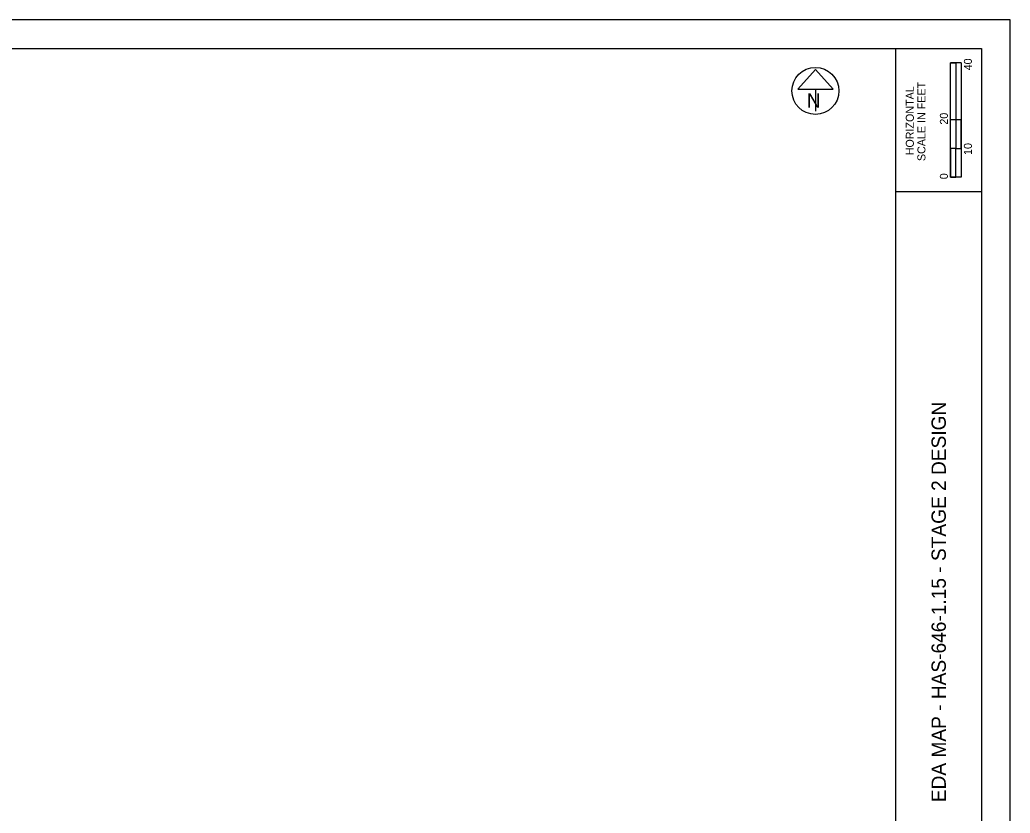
# Model space of a CAD drawing. Extents: x 117359.7 to 117393.7, y 12355.1 to 12408.1.
# Drawn here: x 117376.39 to 117393.71, y 12394.19 to 12408.06 of the extents above; entities that cross this region are included whole.
import ezdxf

# ---------------------------------------------------------------- set-up
doc = ezdxf.new("R2010")
doc.units = 0
for name, color, linetype in [('SH_Border', 7, 'Continuous'), ('SH_Cut_Line', 7, 'Continuous'), ('SH_Data', 7, 'Continuous'), ('SH_Masking', 7, 'Continuous'), ('SH_Text', 7, 'Continuous')]:
    doc.layers.add(name, color=color, linetype=linetype)

msp = doc.modelspace()

# ---------------------------------------------------------------- linework, layer by layer
at = {"layer": 'SH_Border'}
for p, q in [((117391.708, 12386.562), (117391.708, 12407.562)), ((117391.708, 12405.062), (117393.208, 12405.062))]:
    msp.add_line(p, q, dxfattribs=at)
msp.add_lwpolyline([(117361.208, 12407.562), (117393.208, 12407.562), (117393.208, 12386.562), (117361.208, 12386.562)], close=True, dxfattribs=at)
at = {"layer": 'SH_Cut_Line'}
msp.add_lwpolyline([(117359.708, 12386.062), (117393.708, 12386.062), (117393.708, 12408.062), (117359.708, 12408.062)], close=True, dxfattribs=at)
at = {"layer": 'SH_Data'}
for p, q in [((117392.665, 12405.312), (117392.665, 12407.312)), ((117392.853, 12407.312), (117392.665, 12407.312)), ((117392.665, 12406.312), (117392.665, 12407.312)), ((117392.665, 12407.312), (117392.758, 12407.312)), ((117392.758, 12407.312), (117392.759, 12407.312)), ((117392.759, 12407.312), (117392.759, 12406.312)), ((117392.853, 12407.312), (117392.853, 12405.312)), ((117392.759, 12406.312), (117392.665, 12406.312)), ((117392.852, 12406.312), (117392.758, 12406.312)), ((117392.758, 12406.312), (117392.758, 12405.812)), ((117392.852, 12405.812), (117392.852, 12406.312)), ((117392.758, 12405.812), (117392.665, 12405.812)), ((117392.665, 12405.812), (117392.665, 12405.312)), ((117392.758, 12405.812), (117392.852, 12405.812)), ((117392.758, 12405.312), (117392.758, 12405.812)), ((117392.853, 12405.312), (117392.665, 12405.312)), ((117392.665, 12405.312), (117392.758, 12405.312))]:
    msp.add_line(p, q, dxfattribs=at)
at = {"layer": 'SH_Masking'}
msp.add_circle((117390.302, 12406.819), 0.41, dxfattribs=at)
at = {"layer": 'SH_Text'}
for p, q in [((117390.302, 12407.193), (117389.995, 12406.852)), ((117390.61, 12406.852), (117390.302, 12407.193)), ((117389.995, 12406.852), (117390.61, 12406.852)), ((117390.302, 12406.852), (117390.302, 12406.465))]:
    msp.add_line(p, q, dxfattribs=at)
msp.add_circle((117390.302, 12406.819), 0.41, dxfattribs=at)

# ---------------------------------------------------------------- texts
at = {"layer": 'SH_Data'}
for s, height, p in [('40', 0.14, (117393.039, 12407.179)), ('SCALE IN FEET', 0.14, (117392.226, 12405.592)), ('HORIZONTAL', 0.14, (117392.023, 12405.693)), ('20', 0.14, (117392.619, 12406.229)), ('10', 0.14, (117393.039, 12405.699)), ('0', 0.14, (117392.619, 12405.274)), ('EDA MAP - HAS-646-1.15 - STAGE 2 DESIGN', 0.25, (117392.583, 12394.379))]:
    msp.add_text(s, height=height, rotation=90, dxfattribs=at).set_placement(p)
at = {"layer": 'SH_Text'}
msp.add_text('N', height=0.25, dxfattribs=at).set_placement((117390.151, 12406.528))

doc.saveas('drawing.dxf')
